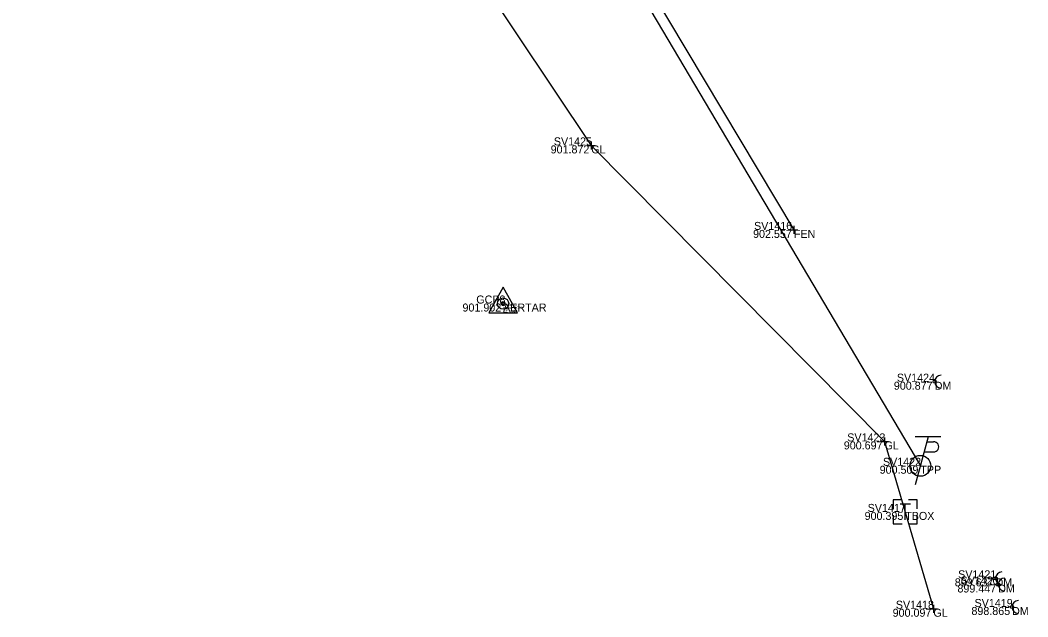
# Model space of a CAD drawing. Extents: x 1918148 to 1919797, y 624701 to 627089.
# Drawn here: x 1918904 to 1919029.8, y 625312.6 to 625387.1 of the extents above; entities that cross this region are included whole.
import ezdxf

# ---------------------------------------------------------------- set-up
doc = ezdxf.new("R2010")
doc.units = 0
for name, color, linetype in [('_CIVIL_CONSTRUCTION', 7, 'Continuous'), ('RD_X_Fence', 7, 'Continuous'), ('SV_P_Aerial_Targets', 7, 'Continuous'), ('SV_P_Control_Cells_Set', 7, 'Continuous'), ('SV_X_Shot_Marker', 7, 'Continuous'), ('SV_X_Text_Comment', 7, 'Continuous'), ('SV_X_Text_Elevation', 7, 'Continuous'), ('SV_X_Text_Name', 7, 'Continuous'), ('UT_X_Gas', 7, 'Continuous'), ('UT_X_Misc_Cells', 7, 'Continuous'), ('UT_X_Overhead_Combined', 7, 'Continuous'), ('UT_X_Telecom_Cells', 7, 'Continuous')]:
    doc.layers.add(name, color=color, linetype=linetype)

msp = doc.modelspace()

# ---------------------------------------------------------------- linework, layer by layer
at = {"layer": '_CIVIL_CONSTRUCTION'}
msp.add_line((1918964.29, 625351.71), (1918964.29, 625351.71), dxfattribs=at)
msp.add_circle((1918964.29, 625351.71), 0.25, dxfattribs=at)
at = {"layer": 'RD_X_Fence'}
msp.add_lwpolyline([(1918745.79, 625786.43), (1918772.78, 625741.75), (1918796.76, 625701.53), (1918837.42, 625633.44), (1918845.82, 625619.99), (1919000.61, 625360.91)], dxfattribs=at)
at = {"layer": 'SV_P_Aerial_Targets'}
msp.add_line((1918964.29, 625351.71), (1918964.29, 625351.71), dxfattribs=at)
msp.add_lwpolyline([(1918962.49, 625350.55), (1918966.09, 625350.55), (1918964.29, 625353.77)], close=True, dxfattribs=at)
for radius in [0.7, 0.16]:
    msp.add_circle((1918964.29, 625351.71), radius, dxfattribs=at)
at = {"layer": 'SV_P_Control_Cells_Set'}
msp.add_line((1918964.29, 625351.71), (1918964.29, 625351.71), dxfattribs=at)
at = {"layer": 'SV_X_Shot_Marker'}
for p, q in [((1918974.8, 625371.47), (1918975.8, 625371.47)), ((1918975.3, 625371.97), (1918975.3, 625370.97)), ((1918975.3, 625371.47), (1918975.3, 625371.47)), ((1919000.61, 625361.41), (1919000.61, 625360.41)), ((1919000.11, 625360.91), (1919001.11, 625360.91)), ((1919000.61, 625360.91), (1919000.61, 625360.91)), ((1919011.93, 625334.98), (1919011.93, 625333.98)), ((1919011.43, 625334.48), (1919012.43, 625334.48)), ((1919011.93, 625334.48), (1919011.93, 625334.48)), ((1919017.53, 625313.57), (1919018.53, 625313.57)), ((1919018.03, 625314.07), (1919018.03, 625313.07)), ((1919018.03, 625313.57), (1919018.03, 625313.57))]:
    msp.add_line(p, q, dxfattribs=at)
at = {"layer": 'UT_X_Gas'}
msp.add_lwpolyline([(1918759.17, 625917.08), (1918754.31, 625900.24), (1918749.45, 625846.76), (1918748.46, 625829), (1918743.94, 625797.46), (1918743.01, 625773.57), (1918765.83, 625740.86), (1918795.68, 625692.78), (1918822.43, 625647.51), (1918838.93, 625617.6), (1918864.37, 625571.21), (1918888.36, 625525.76), (1918914.14, 625478.38), (1918935.19, 625439.32), (1918956.47, 625399.66), (1918975.3, 625371.47), (1919011.93, 625334.48), (1919018.03, 625313.57)], dxfattribs=at)
at = {"layer": 'UT_X_Misc_Cells'}
for p, q in [((1919017.37, 625335.04), (1919015.76, 625329.04)), ((1919018.97, 625335.04), (1919015.77, 625335.04)), ((1919017.21, 625334.43), (1919018.06, 625334.43)), ((1919016.87, 625333.16), (1919018.06, 625333.16))]:
    msp.add_line(p, q, dxfattribs=at)
for centre, radius in [((1919018.19, 625341.94), 0.2), ((1919016.4, 625331.43), 1.3), ((1919025.79, 625317.37), 0.2), ((1919026.12, 625316.6), 0.2), ((1919027.85, 625313.79), 0.2)]:
    msp.add_circle(centre, radius, dxfattribs=at)
for centre, radius, start, end in [((1919018.99, 625341.94), 0.8, 90, 270), ((1919018.07, 625333.8), 0.638, 268.8767, 91.1233), ((1919026.59, 625317.37), 0.8, 90, 270), ((1919026.93, 625316.6), 0.8, 90, 270), ((1919028.65, 625313.79), 0.8, 90, 270)]:
    msp.add_arc(centre, radius, start, end, dxfattribs=at)
at = {"layer": 'UT_X_Overhead_Combined'}
msp.add_lwpolyline([(1918749.03, 625800.12), (1918759.42, 625761.9), (1918898.02, 625531.27), (1919016.4, 625331.43)], dxfattribs=at)
at = {"layer": 'UT_X_Telecom_Cells'}
for p, q in [((1919013.86, 625326.67), (1919015.17, 625326.67)), ((1919014.51, 625324.67), (1919014.51, 625326.67)), ((1919014.51, 625325.67), (1919014.51, 625325.67))]:
    msp.add_line(p, q, dxfattribs=at)
for points in [[(1919014.11, 625327.17), (1919013.01, 625327.17), (1919013.01, 625326.07)], [(1919016.01, 625326.07), (1919016.01, 625327.17), (1919014.92, 625327.17)], [(1919013.01, 625325.27), (1919013.01, 625324.17), (1919014.11, 625324.17)], [(1919014.92, 625324.17), (1919016.01, 625324.17), (1919016.01, 625325.27)]]:
    msp.add_lwpolyline(points, dxfattribs=at)

# ---------------------------------------------------------------- texts
at = {"layer": '_CIVIL_CONSTRUCTION'}
for s, p in [('Index: 13', (1918964.29, 625351.41)), ('Name: GCP8', (1918964.29, 625351.01)), ('ΔZ: 0.017', (1918964.29, 625350.61))]:
    msp.add_text(s, height=0.3, dxfattribs=at).set_placement(p)
at = {"layer": 'SV_X_Text_Comment'}
for s, p in [('GL', (1918975.3, 625370.47)), ('FEN', (1919000.61, 625359.91)), ('AERTAR', (1918964.29, 625350.71)), ('DM', (1919018.19, 625340.94)), ('GL', (1919011.93, 625333.48)), ('TPP', (1919016.4, 625330.44)), ('TBOX', (1919014.51, 625324.67)), ('DM', (1919025.79, 625316.37)), ('DM', (1919026.12, 625315.6)), ('GL', (1919018.03, 625312.57)), ('DM', (1919027.85, 625312.79))]:
    msp.add_text(s, height=1, dxfattribs=at).set_placement(p)
at = {"layer": 'SV_X_Text_Elevation'}
for s, p in [('901.872', (1918970.23, 625370.47)), ('902.557', (1918995.51, 625359.91)), ('901.902', (1918959.22, 625350.71)), ('900.877', (1919013.09, 625340.94)), ('900.697', (1919006.84, 625333.48)), ('900.509', (1919011.32, 625330.44)), ('900.395', (1919009.44, 625324.67)), ('899.637', (1919020.7, 625316.37)), ('899.447', (1919021.03, 625315.6)), ('900.097', (1919012.94, 625312.57)), ('898.865', (1919022.78, 625312.79))]:
    msp.add_text(s, height=1, dxfattribs=at).set_placement(p)
at = {"layer": 'SV_X_Text_Name'}
for s, p in [('SV1425', (1918970.63, 625371.47)), ('SV1416', (1918995.63, 625360.91)), ('GCP8', (1918960.94, 625351.71)), ('SV1424', (1919013.47, 625341.94)), ('SV1423', (1919007.27, 625334.48)), ('SV1422', (1919011.73, 625331.43)), ('SV1417', (1919009.82, 625325.67)), ('SV1421', (1919021.12, 625317.37)), ('SV1420', (1919021.41, 625316.6)), ('SV1419', (1919023.17, 625313.79)), ('SV1418', (1919013.34, 625313.57))]:
    msp.add_text(s, height=1, dxfattribs=at).set_placement(p)

doc.saveas('drawing.dxf')
